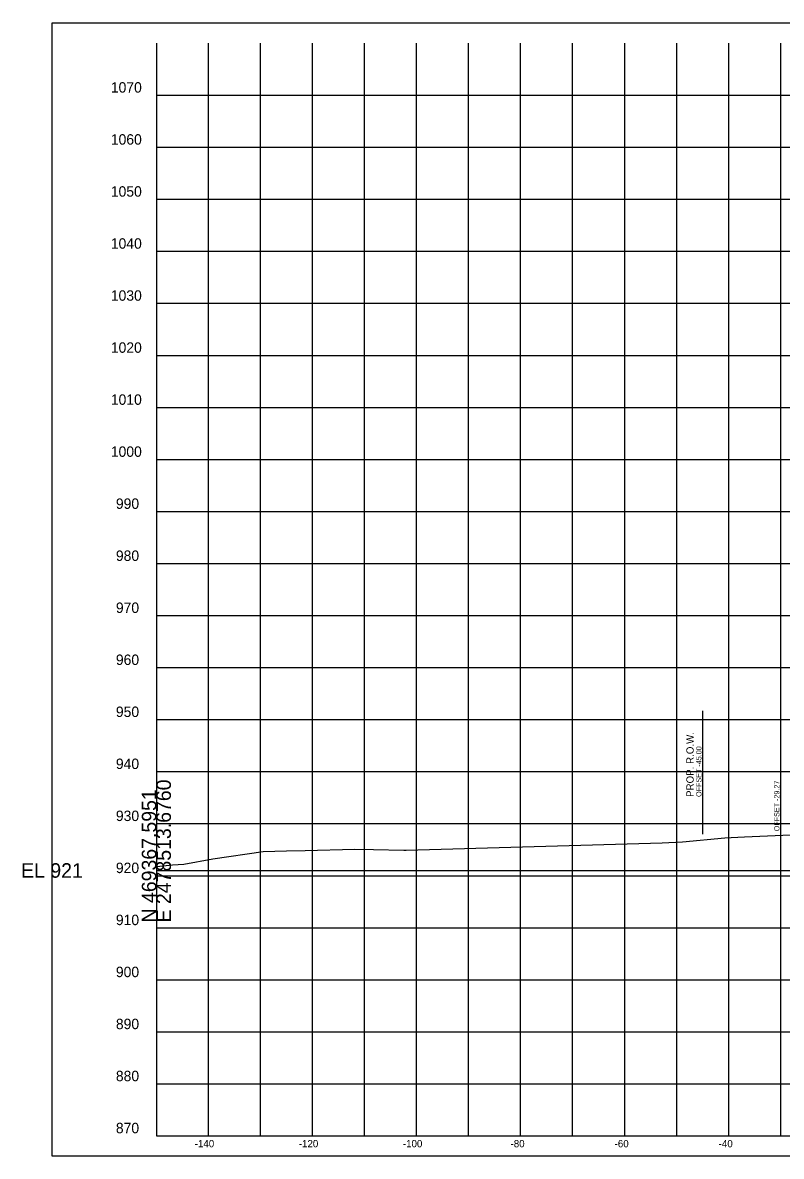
# Model space of a CAD drawing. Extents: x -26 to 2478923, y -10 to 469990.
# Drawn here: x -25.7 to 120.1, y 9445.1 to 9662.9 of the extents above; entities that cross this region are included whole.
import ezdxf

# ---------------------------------------------------------------- set-up
doc = ezdxf.new("R2010")
doc.units = 0
for name, color, linetype in [('DESIGN - ROW - Right-of-Way and Easement Labels', 7, 'Continuous'), ('DESIGN - ROW - Right-of-Way Linework', 7, 'Continuous'), ('DESIGN - SHEET - Corner Text', 7, 'Continuous'), ('DESIGN - SHEET - Light Grid', 7, 'Continuous'), ('DESIGN - SHEET - Linework', 7, 'Continuous'), ('DESIGN - SHEET - Plot Shape', 7, 'Continuous'), ('DESIGN - TYPICAL - Slope Tie Text', 7, 'Continuous'), ('SURVEY - GROUND - Top of Ground', 7, 'Continuous')]:
    doc.layers.add(name, color=color, linetype=linetype)

msp = doc.modelspace()

# ---------------------------------------------------------------- linework, layer by layer
at = {"layer": 'DESIGN - ROW - Right-of-Way Linework'}
msp.add_line((105, 9506.95), (105, 9530.65), dxfattribs=at)
at = {"layer": 'DESIGN - SHEET - Light Grid'}
msp.add_line((0, 9500), (150, 9500), dxfattribs=at)
at = {"layer": 'DESIGN - SHEET - Linework'}
for p, q in [((10, 9449), (10, 9659)), ((10, 9449), (10, 9659)), ((10, 9449), (10, 9659)), ((10, 9449), (10, 9659)), ((20, 9449), (20, 9659)), ((20, 9449), (20, 9659)), ((20, 9449), (20, 9659)), ((20, 9449), (20, 9659)), ((30, 9449), (30, 9659)), ((30, 9449), (30, 9659)), ((30, 9449), (30, 9659)), ((30, 9449), (30, 9659)), ((40, 9449), (40, 9659)), ((40, 9449), (40, 9659)), ((40, 9449), (40, 9659)), ((40, 9449), (40, 9659)), ((50, 9449), (50, 9659)), ((50, 9449), (50, 9659)), ((50, 9449), (50, 9659)), ((50, 9449), (50, 9659)), ((60, 9449), (60, 9659)), ((60, 9449), (60, 9659)), ((60, 9449), (60, 9659)), ((60, 9449), (60, 9659)), ((70, 9449), (70, 9659)), ((70, 9449), (70, 9659)), ((70, 9449), (70, 9659)), ((70, 9449), (70, 9659)), ((80, 9449), (80, 9659)), ((80, 9449), (80, 9659)), ((80, 9449), (80, 9659)), ((80, 9449), (80, 9659)), ((90, 9449), (90, 9659)), ((90, 9449), (90, 9659)), ((90, 9449), (90, 9659)), ((90, 9449), (90, 9659)), ((100, 9449), (100, 9659)), ((100, 9449), (100, 9659)), ((100, 9449), (100, 9659)), ((100, 9449), (100, 9659)), ((110, 9449), (110, 9659)), ((110, 9449), (110, 9659)), ((110, 9449), (110, 9659)), ((110, 9449), (110, 9659)), ((120, 9449), (120, 9659)), ((120, 9449), (120, 9659)), ((120, 9449), (120, 9659)), ((120, 9449), (120, 9659)), ((0, 9649), (300, 9649)), ((0, 9649), (300, 9649)), ((0, 9649), (300, 9649)), ((0, 9649), (300, 9649)), ((0, 9639), (300, 9639)), ((0, 9639), (300, 9639)), ((0, 9639), (300, 9639)), ((0, 9639), (300, 9639)), ((0, 9629), (300, 9629)), ((0, 9629), (300, 9629)), ((0, 9629), (300, 9629)), ((0, 9629), (300, 9629)), ((0, 9619), (300, 9619)), ((0, 9619), (300, 9619)), ((0, 9619), (300, 9619)), ((0, 9619), (300, 9619)), ((0, 9609), (300, 9609)), ((0, 9609), (300, 9609)), ((0, 9609), (300, 9609)), ((0, 9609), (300, 9609)), ((0, 9599), (300, 9599)), ((0, 9599), (300, 9599)), ((0, 9599), (300, 9599)), ((0, 9599), (300, 9599)), ((0, 9589), (300, 9589)), ((0, 9589), (300, 9589)), ((0, 9589), (300, 9589)), ((0, 9589), (300, 9589)), ((0, 9579), (300, 9579)), ((0, 9579), (300, 9579)), ((0, 9579), (300, 9579)), ((0, 9579), (300, 9579)), ((0, 9569), (300, 9569)), ((0, 9569), (300, 9569)), ((0, 9569), (300, 9569)), ((0, 9569), (300, 9569)), ((0, 9559), (300, 9559)), ((0, 9559), (300, 9559)), ((0, 9559), (300, 9559)), ((0, 9559), (300, 9559)), ((0, 9549), (300, 9549)), ((0, 9549), (300, 9549)), ((0, 9549), (300, 9549)), ((0, 9549), (300, 9549)), ((0, 9539), (300, 9539)), ((0, 9539), (300, 9539)), ((0, 9539), (300, 9539)), ((0, 9539), (300, 9539)), ((0, 9529), (300, 9529)), ((0, 9529), (300, 9529)), ((0, 9529), (300, 9529)), ((0, 9529), (300, 9529)), ((0, 9519), (300, 9519)), ((0, 9519), (300, 9519)), ((0, 9519), (300, 9519)), ((0, 9519), (300, 9519)), ((0, 9509), (300, 9509)), ((0, 9509), (300, 9509)), ((0, 9509), (300, 9509)), ((0, 9509), (300, 9509)), ((0, 9499), (300, 9499)), ((0, 9499), (300, 9499)), ((0, 9499), (300, 9499)), ((0, 9499), (300, 9499)), ((0, 9489), (300, 9489)), ((0, 9489), (300, 9489)), ((0, 9489), (300, 9489)), ((0, 9489), (300, 9489)), ((0, 9479), (300, 9479)), ((0, 9479), (300, 9479)), ((0, 9479), (300, 9479)), ((0, 9479), (300, 9479)), ((0, 9469), (300, 9469)), ((0, 9469), (300, 9469)), ((0, 9469), (300, 9469)), ((0, 9469), (300, 9469)), ((0, 9459), (300, 9459)), ((0, 9459), (300, 9459)), ((0, 9459), (300, 9459)), ((0, 9459), (300, 9459))]:
    msp.add_line(p, q, dxfattribs=at)
msp.add_lwpolyline([(0, 9659), (0, 9449), (300, 9449), (300, 9659)], dxfattribs=at)
msp.add_lwpolyline([(0, 9659), (0, 9449), (300, 9449), (300, 9659)], dxfattribs=at)
msp.add_lwpolyline([(0, 9659), (0, 9449), (300, 9449), (300, 9659)], dxfattribs=at)
msp.add_lwpolyline([(0, 9659), (0, 9449), (300, 9449), (300, 9659)], dxfattribs=at)
at = {"layer": 'DESIGN - SHEET - Plot Shape'}
msp.add_lwpolyline([(-20, 9662.94), (320, 9662.94), (320, 9445.06), (-20, 9445.06)], close=True, dxfattribs=at)
msp.add_lwpolyline([(-20, 9662.94), (320, 9662.94), (320, 9445.06), (-20, 9445.06)], close=True, dxfattribs=at)
msp.add_lwpolyline([(-20, 9662.94), (320, 9662.94), (320, 9445.06), (-20, 9445.06)], close=True, dxfattribs=at)
msp.add_lwpolyline([(-20, 9662.94), (320, 9662.94), (320, 9445.06), (-20, 9445.06)], close=True, dxfattribs=at)
at = {"layer": 'SURVEY - GROUND - Top of Ground'}
msp.add_line((48.03, 9503.9), (97.23, 9505.29), dxfattribs=at)
for points in [[(97.23, 9505.29), (101.1, 9505.49), (109.25, 9506.27), (110.43, 9506.33), (113.04, 9506.45), (123.35, 9506.89)], [(0, 9500.74), (3.09, 9501.07), (5.3, 9501.21), (10.84, 9502.23), (20.54, 9503.67), (25.03, 9503.77), (28.58, 9503.84), (38.13, 9504.08), (41.74, 9504.01), (47.57, 9503.89), (48.03, 9503.9)]]:
    msp.add_lwpolyline(points, dxfattribs=at)

# ---------------------------------------------------------------- texts
at = {"layer": 'DESIGN - ROW - Right-of-Way and Easement Labels'}
for s, height, p in [('PROP. R.O.W.', 1.4, (103.25, 9514.13)), ('OFFSET -45.00', 1, (104.75, 9514.13))]:
    msp.add_text(s, height=height, rotation=90, dxfattribs=at).set_placement(p)
at = {"layer": 'DESIGN - SHEET - Corner Text'}
for s, height, p in [('1070', 2, (-8.75, 9649.5)), ('1070', 2, (-8.75, 9649.5)), ('1070', 2, (-8.75, 9649.5)), ('1070', 2, (-8.75, 9649.5)), ('1060', 2, (-8.75, 9639.5)), ('1060', 2, (-8.75, 9639.5)), ('1060', 2, (-8.75, 9639.5)), ('1060', 2, (-8.75, 9639.5)), ('1050', 2, (-8.75, 9629.5)), ('1050', 2, (-8.75, 9629.5)), ('1050', 2, (-8.75, 9629.5)), ('1050', 2, (-8.75, 9629.5)), ('1040', 2, (-8.75, 9619.5)), ('1040', 2, (-8.75, 9619.5)), ('1040', 2, (-8.75, 9619.5)), ('1040', 2, (-8.75, 9619.5)), ('1030', 2, (-8.75, 9609.5)), ('1030', 2, (-8.75, 9609.5)), ('1030', 2, (-8.75, 9609.5)), ('1030', 2, (-8.75, 9609.5)), ('1020', 2, (-8.75, 9599.5)), ('1020', 2, (-8.75, 9599.5)), ('1020', 2, (-8.75, 9599.5)), ('1020', 2, (-8.75, 9599.5)), ('1010', 2, (-8.75, 9589.5)), ('1010', 2, (-8.75, 9589.5)), ('1010', 2, (-8.75, 9589.5)), ('1010', 2, (-8.75, 9589.5)), ('1000', 2, (-8.75, 9579.5)), ('1000', 2, (-8.75, 9579.5)), ('1000', 2, (-8.75, 9579.5)), ('1000', 2, (-8.75, 9579.5)), ('990', 2, (-7.78, 9569.5)), ('990', 2, (-7.78, 9569.5)), ('990', 2, (-7.78, 9569.5)), ('990', 2, (-7.78, 9569.5)), ('980', 2, (-7.78, 9559.5)), ('980', 2, (-7.78, 9559.5)), ('980', 2, (-7.78, 9559.5)), ('980', 2, (-7.78, 9559.5)), ('970', 2, (-7.78, 9549.5)), ('970', 2, (-7.78, 9549.5)), ('970', 2, (-7.78, 9549.5)), ('970', 2, (-7.78, 9549.5)), ('960', 2, (-7.78, 9539.5)), ('960', 2, (-7.78, 9539.5)), ('960', 2, (-7.78, 9539.5)), ('960', 2, (-7.78, 9539.5)), ('950', 2, (-7.78, 9529.5)), ('950', 2, (-7.78, 9529.5)), ('950', 2, (-7.78, 9529.5)), ('950', 2, (-7.78, 9529.5)), ('940', 2, (-7.78, 9519.5)), ('940', 2, (-7.78, 9519.5)), ('940', 2, (-7.78, 9519.5)), ('940', 2, (-7.78, 9519.5)), ('930', 2, (-7.78, 9509.5)), ('930', 2, (-7.78, 9509.5)), ('930', 2, (-7.78, 9509.5)), ('930', 2, (-7.78, 9509.5)), ('920', 2, (-7.78, 9499.5)), ('920', 2, (-7.78, 9499.5)), ('920', 2, (-7.78, 9499.5)), ('920', 2, (-7.78, 9499.5)), ('910', 2, (-7.78, 9489.5)), ('910', 2, (-7.78, 9489.5)), ('910', 2, (-7.78, 9489.5)), ('910', 2, (-7.78, 9489.5)), ('900', 2, (-7.78, 9479.5)), ('900', 2, (-7.78, 9479.5)), ('900', 2, (-7.78, 9479.5)), ('900', 2, (-7.78, 9479.5)), ('890', 2, (-7.78, 9469.5)), ('890', 2, (-7.78, 9469.5)), ('890', 2, (-7.78, 9469.5)), ('890', 2, (-7.78, 9469.5)), ('880', 2, (-7.78, 9459.5)), ('880', 2, (-7.78, 9459.5)), ('880', 2, (-7.78, 9459.5)), ('880', 2, (-7.78, 9459.5)), ('870', 2, (-7.78, 9449.5)), ('870', 2, (-7.78, 9449.5)), ('870', 2, (-7.78, 9449.5)), ('870', 2, (-7.78, 9449.5)), ('-140', 1.4, (7.37, 9446.8)), ('-140', 1.4, (7.37, 9446.8)), ('-140', 1.4, (7.37, 9446.8)), ('-140', 1.4, (7.37, 9446.8)), ('-120', 1.4, (27.37, 9446.8)), ('-120', 1.4, (27.37, 9446.8)), ('-120', 1.4, (27.37, 9446.8)), ('-120', 1.4, (27.37, 9446.8)), ('-100', 1.4, (47.37, 9446.8)), ('-100', 1.4, (47.37, 9446.8)), ('-100', 1.4, (47.37, 9446.8)), ('-100', 1.4, (47.37, 9446.8)), ('-80', 1.4, (68.06, 9446.8)), ('-80', 1.4, (68.06, 9446.8)), ('-80', 1.4, (68.06, 9446.8)), ('-80', 1.4, (68.06, 9446.8)), ('-60', 1.4, (88.06, 9446.8)), ('-60', 1.4, (88.06, 9446.8)), ('-60', 1.4, (88.06, 9446.8)), ('-60', 1.4, (88.06, 9446.8)), ('-40', 1.4, (108.06, 9446.8)), ('-40', 1.4, (108.06, 9446.8)), ('-40', 1.4, (108.06, 9446.8)), ('-40', 1.4, (108.06, 9446.8))]:
    msp.add_text(s, height=height, dxfattribs=at).set_placement(p)
at = {"layer": 'DESIGN - SHEET - Light Grid'}
for s, p in [('E 2478513.6760', (2.8, 9490)), ('N 469367.5951', (0, 9490))]:
    msp.add_text(s, height=2.8, rotation=90, dxfattribs=at).set_placement(p)
msp.add_text('EL 921', height=2.8, dxfattribs=at).set_placement((-26, 9498.6))
at = {"layer": 'DESIGN - TYPICAL - Slope Tie Text'}
msp.add_text('OFFSET -29.27', height=1, rotation=90, dxfattribs=at).set_placement((119.73, 9507.53))

doc.saveas('drawing.dxf')
